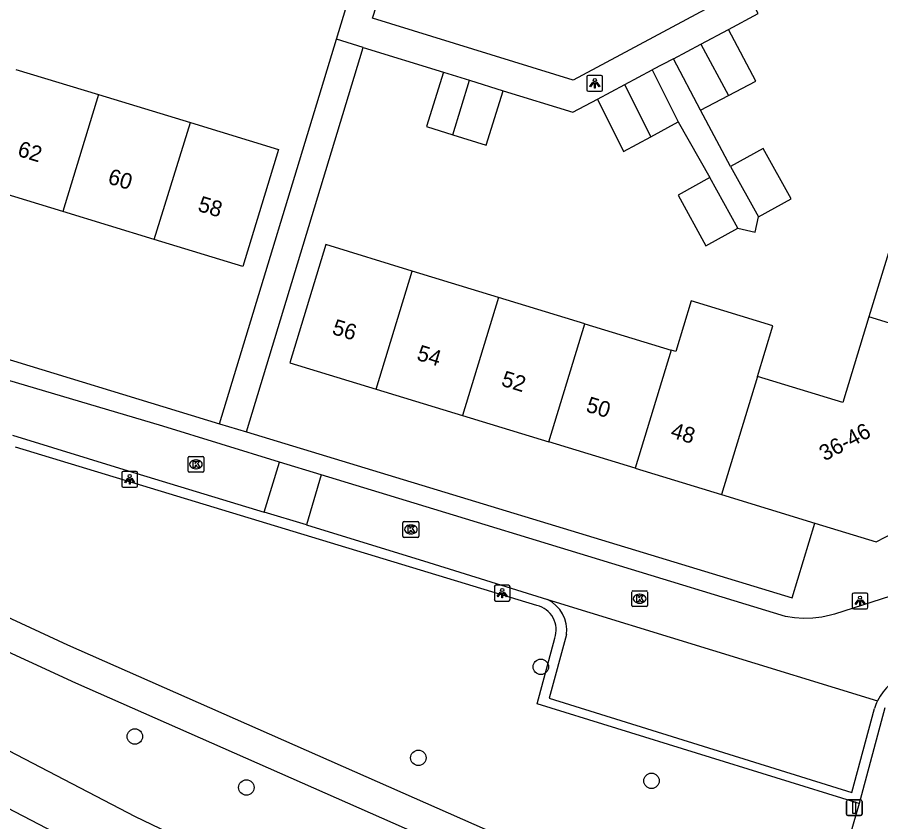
# Model space of a CAD drawing. Extents: x 160304 to 160954, y 383686 to 384161.
# Drawn here: x 160632.9 to 160687.5, y 383779.8 to 383830.6 of the extents above; entities that cross this region are included whole.
import ezdxf

# ---------------------------------------------------------------- set-up
doc = ezdxf.new("R2010")
doc.units = 0
for name, color, linetype in [('IMGEO_Boom', 7, 'Continuous'), ('IMGEO_Greppel_droge_sloot', 7, 'Continuous'), ('IMGEO_Kolk', 7, 'Continuous'), ('IMGEO_Lichtpunt', 7, 'Continuous'), ('IMGEO_Pand', 7, 'Continuous'), ('IMGEO_Pand_nummerreeks', 7, 'Continuous'), ('IMGEO_Rijbaan_lokaal_open', 7, 'Continuous'), ('IMGEO_Verkeersbordpaal', 7, 'Continuous'), ('IMGEO_Voetpad_halfverhard', 7, 'Continuous'), ('IMGEO_Voetpad_open', 7, 'Continuous')]:
    doc.layers.add(name, color=color, linetype=linetype)

msp = doc.modelspace()

# ---------------------------------------------------------------- linework, layer by layer
at = {"layer": 'IMGEO_Boom'}
for centre in [(160665.963, 383789.544), (160640.291, 383785.142), (160658.219, 383783.791), (160672.964, 383782.338), (160647.344, 383781.917)]:
    msp.add_circle(centre, 0.489, dxfattribs=at)
at = {"layer": 'IMGEO_Greppel_droge_sloot'}
for points in [[(160684.972, 383756.649), (160685.542, 383758.679), (160664.695, 383768.884), (160649.742, 383775.545), (160640.34, 383780.06), (160622.299, 383789.443), (160610.062, 383796.203), (160600.019, 383802.155), (160582.534, 383812.776), (160565.781, 383823.661), (160558.345, 383828.766), (160555.752, 383830.697), (160527.152, 383851.99), (160512.051, 383860.483)], [(160684.972, 383756.649), (160662.889, 383766.429), (160648.339, 383772.659), (160639.606, 383776.783), (160620.915, 383786.51), (160608.496, 383793.387), (160598.802, 383799.175), (160580.761, 383810.015), (160564.334, 383820.679), (160556.064, 383826.306), (160553.11, 383828.476), (160524.459, 383849.529), (160508.125, 383858.628)]]:
    msp.add_lwpolyline(points, dxfattribs=at)
at = {"layer": 'IMGEO_Kolk'}
for p, q in [((160643.654, 383801.919), (160643.654, 383802.771)), ((160643.729, 383802.845), (160644.581, 383802.845)), ((160644.142, 383802.625), (160644.167, 383802.625)), ((160644.655, 383802.771), (160644.655, 383801.919)), ((160644.581, 383801.845), (160643.729, 383801.845)), ((160644.165, 383802.065), (160644.14, 383802.065)), ((160657.246, 383797.802), (160657.246, 383798.654)), ((160657.321, 383798.728), (160658.173, 383798.728)), ((160658.247, 383798.654), (160658.247, 383797.802)), ((160657.734, 383798.508), (160657.759, 383798.508)), ((160658.173, 383797.728), (160657.321, 383797.728)), ((160657.757, 383797.948), (160657.732, 383797.948)), ((160671.715, 383793.422), (160671.715, 383794.274)), ((160671.79, 383794.348), (160672.642, 383794.348)), ((160672.716, 383794.274), (160672.716, 383793.422)), ((160672.203, 383794.128), (160672.228, 383794.128)), ((160672.642, 383793.348), (160671.79, 383793.348)), ((160672.226, 383793.568), (160672.201, 383793.568))]:
    msp.add_line(p, q, dxfattribs=at)
for points in [[(160643.654, 383801.919), (160643.654, 383802.771)], [(160643.729, 383802.845), (160644.581, 383802.845)], [(160643.975, 383802.545), (160644.098, 383802.545), (160644.098, 383802.394), (160644.228, 383802.545), (160644.392, 383802.545), (160644.246, 383802.394), (160644.399, 383802.145), (160644.247, 383802.145), (160644.162, 383802.309), (160644.098, 383802.242), (160644.098, 383802.145), (160643.975, 383802.145), (160643.975, 383802.545)], [(160644.655, 383802.771), (160644.655, 383801.919)], [(160644.581, 383801.845), (160643.729, 383801.845)], [(160657.246, 383797.802), (160657.246, 383798.654)], [(160657.321, 383798.728), (160658.173, 383798.728)], [(160658.247, 383798.654), (160658.247, 383797.802)], [(160657.567, 383798.428), (160657.69, 383798.428), (160657.69, 383798.277), (160657.82, 383798.428), (160657.984, 383798.428), (160657.838, 383798.277), (160657.991, 383798.028), (160657.839, 383798.028), (160657.754, 383798.192), (160657.69, 383798.125), (160657.69, 383798.028), (160657.567, 383798.028), (160657.567, 383798.428)], [(160658.173, 383797.728), (160657.321, 383797.728)], [(160671.715, 383793.422), (160671.715, 383794.274)], [(160671.79, 383794.348), (160672.642, 383794.348)], [(160672.716, 383794.274), (160672.716, 383793.422)], [(160672.036, 383794.048), (160672.159, 383794.048), (160672.159, 383793.897), (160672.289, 383794.048), (160672.453, 383794.048), (160672.307, 383793.897), (160672.46, 383793.648), (160672.308, 383793.648), (160672.223, 383793.812), (160672.159, 383793.745), (160672.159, 383793.648), (160672.036, 383793.648), (160672.036, 383794.048)], [(160672.642, 383793.348), (160671.79, 383793.348)]]:
    msp.add_lwpolyline(points, dxfattribs=at)
for centre, start, end in [((160643.731, 383802.769), 91.552, 178.448), ((160643.731, 383802.769), 91.552, 178.448), ((160644.579, 383802.769), 1.552, 88.448), ((160644.579, 383802.769), 1.552, 88.448), ((160643.731, 383801.921), 181.552, 268.448), ((160643.731, 383801.921), 181.552, 268.448), ((160644.579, 383801.921), 271.552, 358.448), ((160644.579, 383801.921), 271.552, 358.448), ((160657.323, 383798.652), 91.552, 178.448), ((160657.323, 383798.652), 91.552, 178.448), ((160658.171, 383798.652), 1.552, 88.448), ((160658.171, 383798.652), 1.552, 88.448), ((160657.323, 383797.804), 181.552, 268.448), ((160657.323, 383797.804), 181.552, 268.448), ((160658.171, 383797.804), 271.552, 358.448), ((160658.171, 383797.804), 271.552, 358.448), ((160671.792, 383794.272), 91.552, 178.448), ((160671.792, 383794.272), 91.552, 178.448), ((160672.64, 383794.272), 1.552, 88.448), ((160672.64, 383794.272), 1.552, 88.448), ((160671.792, 383793.424), 181.552, 268.448), ((160671.792, 383793.424), 181.552, 268.448), ((160672.64, 383793.424), 271.552, 358.448), ((160672.64, 383793.424), 271.552, 358.448)]:
    msp.add_arc(centre, 0.0765, start, end, dxfattribs=at)
for centre, major_axis, ratio, start_param, end_param in [((160644.141, 383802.345), (-0.387, 0.002), 0.722429, 4.712389, 7.853982), ((160644.166, 383802.345), (-0.39, 0.002), 0.717154, 1.570796, 4.712389), ((160657.733, 383798.228), (-0.387, 0.002), 0.722429, 4.712389, 7.853982), ((160657.758, 383798.228), (-0.39, 0.002), 0.717154, 1.570796, 4.712389), ((160672.202, 383793.848), (-0.387, 0.002), 0.722429, 4.712389, 7.853982), ((160672.227, 383793.848), (-0.39, 0.002), 0.717154, 1.570796, 4.712389)]:
    msp.add_ellipse(centre, major_axis=major_axis, ratio=ratio, start_param=start_param, end_param=end_param, dxfattribs=at)
at = {"layer": 'IMGEO_Lichtpunt'}
for p, q in [((160668.879, 383826.83), (160668.879, 383826.023)), ((160668.879, 383826.83), (160668.879, 383826.023)), ((160669.781, 383826.925), (160668.973, 383826.925)), ((160669.781, 383826.925), (160668.973, 383826.925)), ((160669.875, 383826.023), (160669.875, 383826.83)), ((160669.875, 383826.023), (160669.875, 383826.83)), ((160668.973, 383825.929), (160669.781, 383825.929)), ((160668.973, 383825.929), (160669.781, 383825.929)), ((160640.367, 383801.896), (160639.559, 383801.896)), ((160640.367, 383801.896), (160639.559, 383801.896)), ((160639.465, 383801.801), (160639.465, 383800.994)), ((160639.465, 383801.801), (160639.465, 383800.994)), ((160640.461, 383800.994), (160640.461, 383801.801)), ((160640.461, 383800.994), (160640.461, 383801.801)), ((160639.559, 383800.9), (160640.367, 383800.9)), ((160639.559, 383800.9), (160640.367, 383800.9)), ((160663.025, 383794.601), (160663.025, 383793.794)), ((160663.025, 383794.601), (160663.025, 383793.794)), ((160663.927, 383794.696), (160663.119, 383794.696)), ((160663.927, 383794.696), (160663.119, 383794.696)), ((160664.021, 383793.794), (160664.021, 383794.601)), ((160664.021, 383793.794), (160664.021, 383794.601)), ((160686.559, 383794.21), (160685.751, 383794.21)), ((160686.559, 383794.21), (160685.751, 383794.21)), ((160663.119, 383793.7), (160663.927, 383793.7)), ((160663.119, 383793.7), (160663.927, 383793.7)), ((160685.657, 383794.115), (160685.657, 383793.308)), ((160685.657, 383794.115), (160685.657, 383793.308)), ((160686.653, 383793.308), (160686.653, 383794.115)), ((160686.653, 383793.308), (160686.653, 383794.115)), ((160685.751, 383793.214), (160686.559, 383793.214)), ((160685.751, 383793.214), (160686.559, 383793.214))]:
    msp.add_line(p, q, dxfattribs=at)
for points in [[(160669.253, 383826.494), (160669.292, 383826.466), (160669.104, 383826.204), (160669.066, 383826.231), (160669.253, 383826.494)], [(160669.355, 383826.446), (160669.402, 383826.446), (160669.402, 383826.124), (160669.355, 383826.124), (160669.355, 383826.446)], [(160669.465, 383826.466), (160669.503, 383826.493), (160669.69, 383826.231), (160669.651, 383826.203), (160669.465, 383826.466)], [(160639.839, 383801.465), (160639.878, 383801.437), (160639.69, 383801.175), (160639.652, 383801.202), (160639.839, 383801.465)], [(160639.941, 383801.417), (160639.988, 383801.417), (160639.988, 383801.095), (160639.941, 383801.095), (160639.941, 383801.417)], [(160640.051, 383801.437), (160640.089, 383801.464), (160640.276, 383801.202), (160640.237, 383801.174), (160640.051, 383801.437)], [(160663.399, 383794.265), (160663.438, 383794.237), (160663.25, 383793.975), (160663.212, 383794.002), (160663.399, 383794.265)], [(160663.501, 383794.217), (160663.548, 383794.217), (160663.548, 383793.895), (160663.501, 383793.895), (160663.501, 383794.217)], [(160663.611, 383794.237), (160663.649, 383794.264), (160663.836, 383794.002), (160663.797, 383793.974), (160663.611, 383794.237)], [(160686.031, 383793.779), (160686.07, 383793.751), (160685.882, 383793.489), (160685.844, 383793.516), (160686.031, 383793.779)], [(160686.133, 383793.731), (160686.18, 383793.731), (160686.18, 383793.409), (160686.133, 383793.409), (160686.133, 383793.731)], [(160686.243, 383793.751), (160686.281, 383793.778), (160686.468, 383793.516), (160686.429, 383793.488), (160686.243, 383793.751)]]:
    msp.add_lwpolyline(points, dxfattribs=at)
for centre in [(160669.378, 383826.628), (160639.964, 383801.599), (160663.524, 383794.399), (160686.156, 383793.913)]:
    msp.add_circle(centre, 0.0994, dxfattribs=at)
for centre, start, end in [((160668.973, 383826.83), 90, 180), ((160668.973, 383826.83), 90, 180), ((160669.781, 383826.83), 0, 90), ((160669.781, 383826.83), 0, 90), ((160668.973, 383826.023), 180, 270), ((160668.973, 383826.023), 180, 270), ((160669.781, 383826.023), 270, 0), ((160669.781, 383826.023), 270, 360), ((160639.559, 383801.801), 90, 180), ((160639.559, 383801.801), 90, 180), ((160640.367, 383801.801), 0, 90), ((160640.367, 383801.801), 0, 90), ((160639.559, 383800.994), 180, 270), ((160639.559, 383800.994), 180, 270), ((160640.367, 383800.994), 270, 0), ((160640.367, 383800.994), 270, 360), ((160663.119, 383794.601), 90, 180), ((160663.119, 383794.601), 90, 180), ((160663.927, 383794.601), 0, 90), ((160663.927, 383794.601), 0, 90), ((160685.751, 383794.115), 90, 180), ((160685.751, 383794.115), 90, 180), ((160686.559, 383794.115), 0, 90), ((160686.559, 383794.115), 0, 90), ((160663.119, 383793.794), 180, 270), ((160663.119, 383793.794), 180, 270), ((160663.927, 383793.794), 270, 0), ((160663.927, 383793.794), 270, 360), ((160685.751, 383793.308), 180, 270), ((160685.751, 383793.308), 180, 270), ((160686.559, 383793.308), 270, 0), ((160686.559, 383793.308), 270, 360)]:
    msp.add_arc(centre, 0.0946, start, end, dxfattribs=at)
at = {"layer": 'IMGEO_Pand'}
for points in [[(160676.091, 383828.904), (160677.836, 383829.832)], [(160677.824, 383825.649), (160679.559, 383826.569), (160677.836, 383829.832)], [(160674.349, 383827.977), (160676.091, 383828.904)], [(160676.091, 383828.904), (160677.824, 383825.649)], [(160676.07, 383824.719), (160674.349, 383827.977)], [(160632.764, 383827.308), (160637.98, 383825.716)], [(160659.817, 383827.123), (160658.735, 383823.687), (160660.408, 383823.173)], [(160659.817, 383827.123), (160661.458, 383826.615)], [(160671.28, 383826.344), (160673.015, 383827.267)], [(160673.015, 383827.267), (160674.661, 383823.984)], [(160660.408, 383823.173), (160661.458, 383826.615)], [(160661.458, 383826.615), (160663.59, 383825.955)], [(160660.408, 383823.173), (160662.511, 383822.526), (160663.59, 383825.955)], [(160669.545, 383825.42), (160671.28, 383826.344)], [(160672.931, 383823.05), (160671.28, 383826.344)], [(160637.98, 383825.716), (160635.725, 383818.327)], [(160637.98, 383825.716), (160643.802, 383823.94)], [(160669.545, 383825.42), (160671.201, 383822.117), (160672.931, 383823.05)], [(160676.07, 383824.719), (160677.824, 383825.649)], [(160643.802, 383823.94), (160649.366, 383822.242), (160647.111, 383814.853), (160641.516, 383816.56)], [(160641.516, 383816.56), (160643.802, 383823.94)], [(160672.931, 383823.05), (160674.661, 383823.984)], [(160679.723, 383817.984), (160681.787, 383819.128), (160680.029, 383822.302), (160677.965, 383821.158)], [(160677.965, 383821.158), (160679.723, 383817.984)], [(160635.725, 383818.327), (160627.376, 383820.875)], [(160676.664, 383820.468), (160674.642, 383819.357), (160676.4, 383816.158), (160678.422, 383817.269)], [(160678.422, 383817.269), (160676.664, 383820.468)], [(160641.516, 383816.56), (160635.725, 383818.327)], [(160688.346, 383817.026), (160686.712, 383811.669)], [(160657.825, 383814.561), (160652.364, 383816.227), (160650.085, 383808.757), (160655.545, 383807.091)], [(160655.545, 383807.091), (160657.825, 383814.561)], [(160663.285, 383812.895), (160657.825, 383814.561)], [(160663.285, 383812.895), (160661.006, 383805.425)], [(160668.746, 383811.229), (160663.285, 383812.895)], [(160679.665, 383807.898), (160680.64, 383811.096), (160675.472, 383812.672), (160674.497, 383809.475), (160674.206, 383809.564)], [(160666.466, 383803.759), (160668.746, 383811.229)], [(160668.746, 383811.229), (160674.206, 383809.564)], [(160686.712, 383811.669), (160685.059, 383806.252), (160679.665, 383807.898)], [(160694.073, 383809.418), (160686.712, 383811.669)], [(160674.206, 383809.564), (160671.927, 383802.092)], [(160679.665, 383807.898), (160677.387, 383800.427)], [(160655.545, 383807.091), (160661.006, 383805.425)], [(160661.006, 383805.425), (160666.466, 383803.759)], [(160671.927, 383802.092), (160666.466, 383803.759)], [(160683.302, 383798.622), (160687.175, 383797.44), (160688.311, 383798.045), (160689.891, 383798.887), (160691.047, 383799.502), (160692.164, 383803.164)], [(160671.927, 383802.092), (160677.387, 383800.427)], [(160677.387, 383800.427), (160683.302, 383798.622)]]:
    msp.add_lwpolyline(points, dxfattribs=at)
at = {"layer": 'IMGEO_Rijbaan_lokaal_open'}
for points in [[(160649.444, 383802.481), (160642.055, 383804.752), (160629.871, 383808.362), (160629.33, 383808.487), (160628.728, 383808.68), (160628.145, 383808.926), (160627.587, 383809.224), (160627.058, 383809.57), (160626.562, 383809.961), (160626.103, 383810.396), (160625.684, 383810.87), (160625.31, 383811.379), (160624.982, 383811.92), (160616.002, 383828.924)], [(160632.544, 383804.181), (160639.862, 383801.938), (160648.47, 383799.311)], [(160648.47, 383799.311), (160649.444, 383802.481)], [(160652.079, 383801.685), (160649.444, 383802.481)], [(160652.079, 383801.685), (160651.135, 383798.527)], [(160703.03, 383795.267), (160702.84, 383795.375), (160701.938, 383795.784), (160701.002, 383796.111), (160700.042, 383796.353), (160699.063, 383796.509), (160698.075, 383796.576), (160697.084, 383796.555), (160696.1, 383796.445), (160695.129, 383796.248), (160694.567, 383796.092), (160684.538, 383792.874), (160684.293, 383792.805), (160683.73, 383792.686), (160683.158, 383792.617), (160682.583, 383792.6), (160682.009, 383792.634), (160681.44, 383792.719), (160657.945, 383799.886), (160652.079, 383801.685)], [(160651.135, 383798.527), (160648.47, 383799.311)], [(160651.135, 383798.527), (160658.883, 383796.149), (160666.388, 383793.796)], [(160666.388, 383793.796), (160687.252, 383787.394)]]:
    msp.add_lwpolyline(points, dxfattribs=at)
msp.add_arc((160690.093, 383786.008), 3.16, 105.2922, 153.9981, dxfattribs=at)
at = {"layer": 'IMGEO_Verkeersbordpaal'}
for p, q in [((160685.388, 383781.141), (160686.178, 383781.141)), ((160686.178, 383781.141), (160685.388, 383781.141)), ((160685.288, 383780.241), (160685.288, 383781.041)), ((160685.288, 383781.041), (160685.288, 383780.241)), ((160686.278, 383781.041), (160686.278, 383780.241)), ((160686.278, 383780.241), (160686.278, 383781.041)), ((160686.178, 383780.141), (160685.388, 383780.141)), ((160685.388, 383780.141), (160686.178, 383780.141))]:
    msp.add_line(p, q, dxfattribs=at)
msp.add_lwpolyline([(160685.708, 383781.016), (160685.858, 383781.016), (160685.858, 383780.266), (160685.708, 383780.266), (160685.708, 383781.016)], dxfattribs=at)
for centre, start, end in [((160685.388, 383781.041), 90, 180), ((160685.388, 383781.041), 90, 180), ((160686.178, 383781.041), 0, 90), ((160686.178, 383781.041), 360, 90), ((160685.388, 383780.241), 180, 270), ((160685.388, 383780.241), 180, 270), ((160686.178, 383780.241), 270, 0), ((160686.178, 383780.241), 270, 0)]:
    msp.add_arc(centre, 0.1, start, end, dxfattribs=at)
at = {"layer": 'IMGEO_Voetpad_halfverhard'}
for points in [[(160564.231, 383837.826), (160603.749, 383806.669), (160613.532, 383800.088), (160623.864, 383794.407), (160627.316, 383792.767), (160636.545, 383788.535), (160684.565, 383767.367), (160696.112, 383762.451), (160700.343, 383760.526)], [(160677.55, 383772.608), (160636.045, 383790.923), (160628.361, 383794.476), (160620.758, 383798.197), (160613.979, 383802.041), (160606.303, 383807.27), (160589.078, 383820.852)], [(160686.088, 383780.908), (160684.44, 383775.176)]]:
    msp.add_lwpolyline(points, dxfattribs=at)
at = {"layer": 'IMGEO_Voetpad_open'}
for points in [[(160606.586, 383859.913), (160602.222, 383857.561), (160608.312, 383846.103), (160626.241, 383812.373), (160626.527, 383811.938), (160626.85, 383811.531), (160627.209, 383811.154), (160627.6, 383810.811), (160628.02, 383810.504), (160628.465, 383810.236), (160628.933, 383810.009), (160629.419, 383809.824), (160629.92, 383809.684), (160630.04, 383809.657), (160645.643, 383804.913)], [(160664.319, 383848.183), (160664.855, 383848.464), (160667.453, 383849.822), (160677.266, 383831.583), (160668.018, 383826.622), (160655.326, 383830.534), (160656.978, 383835.701), (160657.06, 383835.957)], [(160653.036, 383829.224), (160654.59, 383834.285), (160649.562, 383835.841)], [(160677.836, 383829.832), (160679.704, 383830.827), (160677.215, 383835.517)], [(160645.643, 383804.913), (160653.036, 383829.224)], [(160654.739, 383828.696), (160653.036, 383829.224)], [(160647.349, 383804.394), (160654.739, 383828.696)], [(160654.739, 383828.696), (160659.817, 383827.123)], [(160674.349, 383827.977), (160673.015, 383827.267)], [(160663.59, 383825.955), (160667.989, 383824.592), (160669.545, 383825.42)], [(160677.965, 383821.158), (160676.07, 383824.719)], [(160674.661, 383823.984), (160676.664, 383820.468)], [(160678.422, 383817.269), (160679.521, 383817.014), (160679.723, 383817.984)], [(160645.643, 383804.913), (160647.349, 383804.394)], [(160647.349, 383804.394), (160681.863, 383793.899), (160683.302, 383798.622)], [(160665.712, 383793.418), (160632.749, 383803.427)], [(160667.595, 383791.594), (160666.5, 383787.57), (160685.644, 383781.602), (160687.061, 383786.904)], [(160686.088, 383780.908), (160685.879, 383780.972), (160665.729, 383787.196), (160666.847, 383791.357)], [(160687.716, 383786.947), (160686.088, 383780.908)]]:
    msp.add_lwpolyline(points, dxfattribs=at)
for centre, radius, start, end in [((160665.42, 383791.834), 2.188, 353.7142, 63.7435), ((160665.359, 383791.881), 1.577, 340.6176, 77.0659), ((160690.018, 383786.034), 3.083, 153.811, 163.5978)]:
    msp.add_arc(centre, radius, start, end, dxfattribs=at)

# ---------------------------------------------------------------- texts
at = {"layer": 'IMGEO_Pand_nummerreeks'}
for s, rotation, p in [('62', 343.0275, (160632.808, 383821.852)), ('60', 343.0324, (160638.519, 383820.109)), ('58', 343.0324, (160644.212, 383818.372)), ('56', 343.0347, (160652.706, 383810.592)), ('54', 343.0347, (160658.057, 383808.96)), ('52', 343.0347, (160663.404, 383807.328)), ('50', 343.0347, (160668.76, 383805.694)), ('48', 343.0347, (160674.111, 383804.061)), ('36-46', 28.052, (160683.909, 383802.52))]:
    msp.add_text(s, height=1, rotation=rotation, dxfattribs=at).set_placement(p)

doc.saveas('drawing.dxf')
